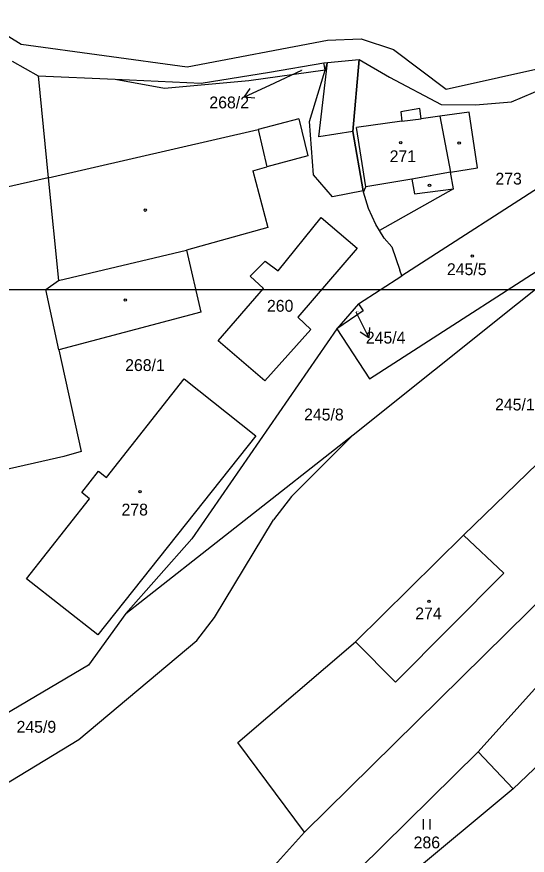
# Model space of a CAD drawing. Extents: x -670359 to -668019, y -978807 to -976674.
# Drawn here: x -669241.5 to -669168.2, y -977081.3 to -976960.8 of the extents above; entities that cross this region are included whole.
import ezdxf

# ---------------------------------------------------------------- set-up
doc = ezdxf.new("R2010")
doc.units = 0
for name, color, linetype in [('Hranice kat_území', 7, 'Continuous'), ('Hranice parcel', 7, 'Continuous'), ('ML1000', 7, 'Continuous'), ('Parcelní čísla', 7, 'Continuous'), ('Vnitřní kresba', 7, 'Continuous'), ('Věcná břemena k části', 7, 'Continuous'), ('Značky budov', 7, 'Continuous'), ('Značky kultur', 7, 'Continuous')]:
    doc.layers.add(name, color=color, linetype=linetype)

msp = doc.modelspace()

# ---------------------------------------------------------------- linework, layer by layer
at = {"layer": 'Hranice kat_území'}
for points in [[(-669247.22, -976960.81), (-669240.83, -976964.74)], [(-669217, -976968.02), (-669196.88, -976964.16)], [(-669196.88, -976964.16), (-669192, -976963.98)], [(-669192, -976963.98), (-669187.38, -976965.49)], [(-669240.83, -976964.74), (-669217, -976968.02)], [(-669187.38, -976965.49), (-669179.8, -976971.21)], [(-669179.8, -976971.21), (-669164.79, -976967.85)]]:
    msp.add_lwpolyline(points, dxfattribs=at)
at = {"layer": 'Hranice parcel'}
for points in [[(-669242.12, -976967.2), (-669238.42, -976969.29)], [(-669227.33, -976969.79), (-669220.25, -976971.06), (-669208.15, -976969.96), (-669197.19, -976968.42), (-669197.39, -976967.45)], [(-669205.2, -976968.79), (-669197.39, -976967.45)], [(-669197.39, -976967.45), (-669196.84, -976967.36)], [(-669196.84, -976967.36), (-669192.3, -976966.95)], [(-669193.24, -976977.3), (-669192.3, -976966.95)], [(-669192.3, -976966.95), (-669187.95, -976969.51)], [(-669214.99, -976970.35), (-669205.2, -976968.79)], [(-669238.42, -976969.29), (-669227.33, -976969.79)], [(-669238.42, -976969.29), (-669236.95, -976983.94)], [(-669227.33, -976969.79), (-669214.99, -976970.35)], [(-669187.95, -976969.51), (-669180.52, -976973.4)], [(-669170.44, -976973.02), (-669162.56, -976969.69)], [(-669183.62, -976974), (-669186.35, -976974.47)], [(-669183.42, -976975.46), (-669183.62, -976974)], [(-669180.52, -976973.4), (-669175.63, -976973.46)], [(-669175.63, -976973.46), (-669170.44, -976973.02)], [(-669186.35, -976974.47), (-669186.17, -976975.81)], [(-669180.72, -976975.1), (-669183.42, -976975.46)], [(-669176.5, -976974.5), (-669180.72, -976975.1)], [(-669175.33, -976982.5), (-669176.5, -976974.5)], [(-669200.96, -976975.46), (-669206.79, -976977.01)], [(-669200.96, -976975.46), (-669199.66, -976980.8)], [(-669186.17, -976975.81), (-669192.68, -976976.7)], [(-669236.95, -976983.94), (-669206.79, -976977.01)], [(-669191.75, -976985.84), (-669193.24, -976977.3)], [(-669191.35, -976985.26), (-669192.68, -976976.7)], [(-669199.66, -976980.8), (-669205.57, -976982.39)], [(-669207.6, -976982.93), (-669205.57, -976982.39)], [(-669207.6, -976982.93), (-669205.44, -976991.07)], [(-669163.76, -976983.58), (-669186.19, -976998.05)], [(-669179.19, -976983.16), (-669175.33, -976982.5)], [(-669178.78, -976985.53), (-669179.19, -976983.16)], [(-669236.95, -976983.94), (-669252.64, -976987.51)], [(-669191.69, -976986.02), (-669191.75, -976985.84)], [(-669191.69, -976986.02), (-669191.35, -976985.26)], [(-669190.98, -976988.36), (-669191.69, -976986.02)], [(-669178.78, -976985.53), (-669189.4, -976991.54)], [(-669189.93, -976990.67), (-669190.98, -976988.36)], [(-669203.96, -976997.31), (-669197.77, -976989.64)], [(-669197.77, -976989.64), (-669192.58, -976994.06)], [(-669189.4, -976991.54), (-669189.93, -976990.67)], [(-669205.44, -976991.07), (-669217.1, -976994.33)], [(-669190.83, -977012.82), (-669158.45, -976991.93)], [(-669188.73, -976992.64), (-669189.4, -976991.54)], [(-669193.15, -977020.88), (-669157.91, -976992.65)], [(-669187.64, -976993.87), (-669188.73, -976992.64)], [(-669217.1, -976994.33), (-669215.05, -977003.27)], [(-669192.58, -976994.06), (-669201.1, -977003.95)], [(-669187.64, -976993.87), (-669186.48, -976997.23)], [(-669207.97, -976998.1), (-669205.8, -976995.94)], [(-669205.8, -976995.94), (-669203.96, -976997.31)], [(-669206.05, -976999.86), (-669207.97, -976998.1)], [(-669192.41, -977002.06), (-669186.19, -976998.05)], [(-669186.19, -976998.05), (-669186.48, -976997.23)], [(-669212.56, -977007.36), (-669206.05, -976999.86)], [(-669192.41, -977002.06), (-669195.5, -977005.65)], [(-669192.41, -977002.06), (-669191.75, -977003.07)], [(-669215.05, -977003.27), (-669235.41, -977008.67)], [(-669201.1, -977003.95), (-669199.26, -977005.72)], [(-669191.75, -977003.07), (-669195.5, -977005.65)], [(-669195.5, -977005.65), (-669216.34, -977035.84)], [(-669199.26, -977005.72), (-669205.85, -977013.14)], [(-669195.5, -977005.65), (-669190.83, -977012.82)], [(-669205.85, -977013.14), (-669212.56, -977007.36)], [(-669235.41, -977008.67), (-669232.21, -977023.27)], [(-669228.6, -977027.01), (-669217.44, -977012.85)], [(-669217.44, -977012.85), (-669207.14, -977021.03)], [(-669207.14, -977021.03), (-669229.81, -977049.62)], [(-669225.82, -977046.53), (-669193.15, -977020.88)], [(-669193.15, -977020.88), (-669202.01, -977029.72)], [(-669142.15, -977020.76), (-669200.15, -977077.96)], [(-669134.22, -977020.78), (-669175.21, -977066.43)], [(-669232.21, -977023.27), (-669234.69, -977024.01)], [(-669234.69, -977024.01), (-669244.67, -977026.22)], [(-669232.15, -977029.18), (-669229.73, -977026.12)], [(-669229.73, -977026.12), (-669228.6, -977027.01)], [(-669231.01, -977030.08), (-669232.15, -977029.18)], [(-669240.06, -977041.57), (-669231.01, -977030.08)], [(-669202.01, -977029.72), (-669204.6, -977033.11)], [(-669213.07, -977047.12), (-669204.6, -977033.11)], [(-669192.85, -977050.62), (-669177.34, -977035.3)], [(-669177.34, -977035.3), (-669171.52, -977040.76)], [(-669216.34, -977035.84), (-669225.82, -977046.53)], [(-669171.52, -977040.76), (-669187.1, -977056.4)], [(-669229.81, -977049.62), (-669240.06, -977041.57)], [(-669225.82, -977046.53), (-669231.17, -977053.95)], [(-669215.61, -977050.43), (-669213.07, -977047.12)], [(-669146.24, -977048.91), (-669170.18, -977071.73)], [(-669232.56, -977064.67), (-669215.61, -977050.43)], [(-669187.1, -977056.4), (-669192.85, -977050.62)], [(-669231.17, -977053.95), (-669248.79, -977064.37)], [(-669258.34, -977080.32), (-669232.56, -977064.67)], [(-669175.21, -977066.43), (-669195.69, -977086.62)], [(-669170.18, -977071.73), (-669175.21, -977066.43)], [(-669170.18, -977071.73), (-669185.64, -977084.61)], [(-669200.15, -977077.96), (-669223.85, -977104.3)]]:
    msp.add_lwpolyline(points, dxfattribs=at)
at = {"layer": 'ML1000'}
msp.add_lwpolyline([(-668750, -977000), (-668750, -977500), (-669375, -977500), (-669375, -977000)], close=True, dxfattribs=at)
at = {"layer": 'Parcelní čísla'}
for p, q in [((-669200.57, -976968.53), (-669205.18, -976970.68)), ((-669207.31, -976972.5), (-669208.8, -976972.38)), ((-669192.78, -977003.21), (-669192.7, -977003.38)), ((-669190.82, -977005.46), (-669190.91, -977006.96))]:
    msp.add_line(p, q, dxfattribs=at)
for points in [[(-669205.18, -976970.68), (-669208.8, -976972.38), (-669207.94, -976971.14)], [(-669192.7, -977003.38), (-669190.91, -977006.96), (-669192.16, -977006.13)]]:
    msp.add_lwpolyline(points, dxfattribs=at)
at = {"layer": 'Vnitřní kresba'}
for points in [[(-669180.72, -976975.1), (-669179.19, -976983.16)], [(-669186.17, -976975.81), (-669183.42, -976975.46)], [(-669206.79, -976977.01), (-669205.57, -976982.39)], [(-669179.19, -976983.16), (-669184.75, -976984.12)], [(-669236.95, -976983.94), (-669235.47, -976998.68)], [(-669184.75, -976984.12), (-669191.35, -976985.26)], [(-669184.75, -976984.12), (-669184.39, -976986.24)], [(-669184.39, -976986.24), (-669178.78, -976985.53)], [(-669235.47, -976998.68), (-669217.1, -976994.33)], [(-669237.31, -977000), (-669235.47, -976998.68)], [(-669235.41, -977008.67), (-669237.31, -977000)], [(-669177.34, -977035.3), (-669140.88, -976999.96)], [(-669209.71, -977065.06), (-669192.85, -977050.62)], [(-669200.15, -977077.96), (-669209.71, -977065.06)]]:
    msp.add_lwpolyline(points, dxfattribs=at)
at = {"layer": 'Věcná břemena k části'}
for p, q in [((-669199.45, -976975.88), (-669196.84, -976967.36)), ((-669196.84, -976967.36), (-669192.3, -976966.95)), ((-669192.3, -976966.95), (-669193.24, -976977.3)), ((-669198.89, -976983.5), (-669199.45, -976975.88)), ((-669193.24, -976977.3), (-669191.75, -976985.84)), ((-669196.13, -976986.68), (-669198.89, -976983.5)), ((-669191.75, -976985.84), (-669196.13, -976986.68))]:
    msp.add_line(p, q, dxfattribs=at)
for points in [[(-669193.24, -976977.3), (-669198.08, -976978.07), (-669196.84, -976967.36)], [(-669196.84, -976967.36), (-669192.3, -976966.95)], [(-669192.3, -976966.95), (-669193.24, -976977.3)]]:
    msp.add_lwpolyline(points, dxfattribs=at)
at = {"layer": 'Značky budov'}
for centre in [(-669186.35, -976978.9), (-669176.07, -976995.19), (-669223.77, -977029.03), (-669182.3, -977044.79)]:
    msp.add_circle(centre, 0.175, dxfattribs=at)
at = {"layer": 'Značky kultur'}
for p, q in [((-669183.1, -977076.09), (-669183.1, -977077.59)), ((-669182.1, -977077.59), (-669182.1, -977076.09))]:
    msp.add_line(p, q, dxfattribs=at)
for centre in [(-669186.35, -976978.9), (-669177.95, -976978.96), (-669182.21, -976985.04), (-669223.02, -976988.59), (-669176.07, -976995.19), (-669225.89, -977001.52), (-669223.77, -977029.03), (-669182.3, -977044.79)]:
    msp.add_circle(centre, 0.175, dxfattribs=at)

# ---------------------------------------------------------------- texts
at = {"layer": 'Parcelní čísla'}
for s, height, p in [('268/2', 0.1, (-669200.77, -976968.53)), ('268/2', 1.7, (-669213.82, -976973.97)), ('271', 1.7, (-669187.93, -976981.7)), ('273', 1.7, (-669172.75, -976984.92)), ('245/5', 1.7, (-669179.71, -976997.93)), ('260', 1.7, (-669205.55, -977003.19)), ('245/4', 0.1, (-669192.78, -977003.21)), ('245/4', 1.7, (-669191.35, -977007.76)), ('268/1', 1.7, (-669225.91, -977011.71)), ('245/1', 1.7, (-669172.8, -977017.37)), ('245/8', 1.7, (-669200.22, -977018.81)), ('278', 1.7, (-669226.43, -977032.47)), ('274', 1.7, (-669184.26, -977047.39)), ('245/9', 1.7, (-669241.5, -977063.68)), ('286', 1.7, (-669184.49, -977080.29))]:
    msp.add_text(s, height=height, dxfattribs=at).set_placement(p)

doc.saveas('drawing.dxf')
